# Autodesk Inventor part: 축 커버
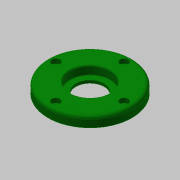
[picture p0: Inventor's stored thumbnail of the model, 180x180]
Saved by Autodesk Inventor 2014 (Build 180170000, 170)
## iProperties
Created: 2015-10
Part Number: 축 커버
Document SubType Name: Modeling
Designer: mdu
Density: 2.71 g/cm^3
Material: Aluminum 6061
Appearance: Dark Green
Mass: 115.032 g
Surface Area: 136.578 cm^2
Volume: 42.4472 cm^3
Author: mdu
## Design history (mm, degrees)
sketch "스케치1"
  geometry: C1 r 40 at (0, 0) reference; C2 r 26 at (0, 0) reference; 1 further point
  node "참조1"
  node "참조2"
extrude "돌출1" new body sketch "스케치1" distance "d0" = 10; taper "d1" = 0 deg
extrude "돌출2" join sketch "스케치1" distance "d2" = 4; taper "d3" = 0 deg
hole "구멍1" diameter "d6" = 27; stored, may be unused: countersink angle "d10" = 90 deg, drill point angle "d12" = 118 deg; dims "d7" = 6, "d8" = 38, "d9" = 8.3, "d11" = 8, "d33" = 10, "d34" = 10
sketch "스케치2"
  geometry: C1 r 20 at (0, 0); 1 further point
  constraints: 1 centre point, 1 coincident
  dimensions: "d13" = 40 diameter of C1
extrude "돌출3" cut sketch "스케치2" distance "d14" = 3; taper "d15" = 0 deg
sketch "스케치3"
  geometry: C1 r 1.621 at (0, 32.5) reference; 1 further point
hole "구멍2" sketch "스케치3" at (0, 32.5) diameter "d16" = 4.5; stored, may be unused: countersink angle "d20" = 90 deg, drill point angle "d22" = 118 deg; dims "d17" = 6, "d18" = 8, "d19" = 4.4, "d21" = 8
fillet "모깎기1" dims "d26" = 3, "d27" = 0.3
chamfer "모따기1" distance "d28" = 1; stored, may be unused: second distance "d29" = 2, angle "d30" = 45 deg
chamfer "모따기2" distance "d31" = 0.8; stored, may be unused: second distance "d32" = 2, angle "d35" = 30 deg
node "솔리드1"
pattern_circular "원형 패턴1" dims angle "d24" = 360 deg
node "참조3"
